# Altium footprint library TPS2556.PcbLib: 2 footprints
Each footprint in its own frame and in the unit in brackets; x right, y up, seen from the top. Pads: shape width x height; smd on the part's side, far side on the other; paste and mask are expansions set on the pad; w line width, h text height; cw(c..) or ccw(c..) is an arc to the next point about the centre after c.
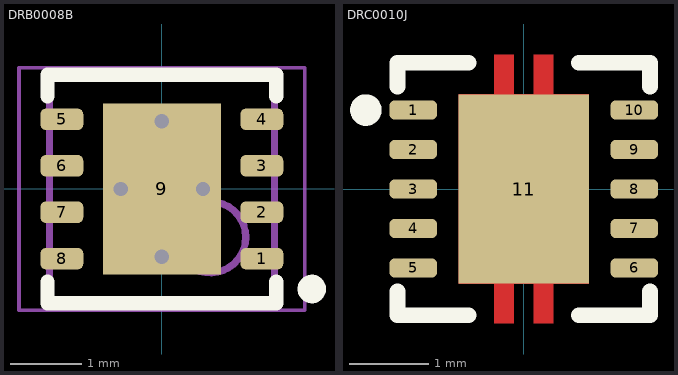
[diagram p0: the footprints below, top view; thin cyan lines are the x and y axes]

## DRB0008B [mm]
pads (9):
  rrect50% 0.6x0.3 smd paste+0 mask+0.07: 1(1.4,-0.975) 2(1.4,-0.325) 3(1.4,0.325) 4(1.4,0.975) 5(-1.4,0.975) 6(-1.4,0.325) 7(-1.4,-0.325) 8(-1.4,-0.975)
  rect 1.65x2.4 smd paste-0.825 mask+0.07: 9(0,0)
via 0,0.95 diameter 0.5 hole 0.2
via 0,-0.95 diameter 0.5 hole 0.2
via 0.575,0 diameter 0.5 hole 0.2
via -0.575,0 diameter 0.5 hole 0.2
Top Overlay:
  circle w0.2: c2.1,-1.4 r0.1
  lines w0.2: -1.6,-1.3 -1.6,-1.6 1.6,-1.6 1.6,-1.3 ; -1.6,1.3 -1.6,1.6 1.6,1.6 1.6,1.3
Top Paste:
  region: 0.735,-0.1 -0.735,-0.1 -0.735,-1.16 0.735,-1.16
  rectangle: -0.735,0.1 0.735,1.16
Mechanical 13:
  circle w0.1: c0.675,-0.675 r0.5
  lines w0.1: -1.575,-1.575 -1.575,1.575 1.575,1.575 1.575,-1.575 -1.575,-1.575
Mechanical 15:
  lines w0.05: -2,-1.7 -2,1.7 2,1.7 2,-1.7 -2,-1.7
  lines w0.1: -0.5,0 0.5,0 ; 0,-0.5 0,0.5
3D body "DRB0008B.stp": height 0.77, standoff 0, extent -1.5,-1.5 1.5,1.5

## DRC0010J [mm]
pads (11):
  rrect50% 0.6x0.24 smd mask+0.05: 1(-1.4,1) 2(-1.4,0.5) 3(-1.4,0) 4(-1.4,-0.5) 5(-1.4,-1) 6(1.4,-1) 7(1.4,-0.5) 8(1.4,0) 9(1.4,0.5) 10(1.4,1)
  rect 1.65x2.4 smd paste-1.2 mask+0.05: 11(0,0)
Top Layer:
  region: -0.375,-1.7 -0.375,-1.2 -0.825,-1.2 -0.825,1.2 -0.375,1.2 -0.375,1.7 -0.125,1.7 -0.125,1.2 0.125,1.2 0.125,1.7 0.375,1.7 0.375,1.2 0.825,1.2 0.825,-1.2 0.375,-1.2 0.375,-1.7 0.125,-1.7 0.125,-1.2 -0.125,-1.2 -0.125,-1.7
Top Overlay:
  circle w0.2: c-2,1 r0.1
  lines w0.2: -1.6,-1.3 -1.6,-1.6 -0.7,-1.6 ; -1.6,1.3 -1.6,1.6 -0.7,1.6 ; 0.7,-1.6 1.6,-1.6 1.6,-1.3 ; 0.7,1.6 1.6,1.6 1.6,1.3
Top Paste:
  rectangle: -0.75,0.15 0.75,1.15
  region: 0.75,-0.15 -0.75,-0.15 -0.75,-1.15 0.75,-1.15
  rectangle: -0.375,-1.7 -0.125,-1.36
  rectangle: 0.125,-1.7 0.375,-1.36
  region: 0.375,1.7 0.125,1.7 0.125,1.36 0.375,1.36
  region: -0.125,1.7 -0.375,1.7 -0.375,1.36 -0.125,1.36
Top Solder:
  rectangle: -0.375,-1.7 -0.125,-1.2
  rectangle: 0.125,-1.7 0.375,-1.2
  region: 0.375,1.7 0.125,1.7 0.125,1.2 0.375,1.2
  region: -0.125,1.7 -0.375,1.7 -0.375,1.2 -0.125,1.2
3D body "DRC0010J.stp": height 1, standoff 0, extent -1.5,-1.5 1.5,1.5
